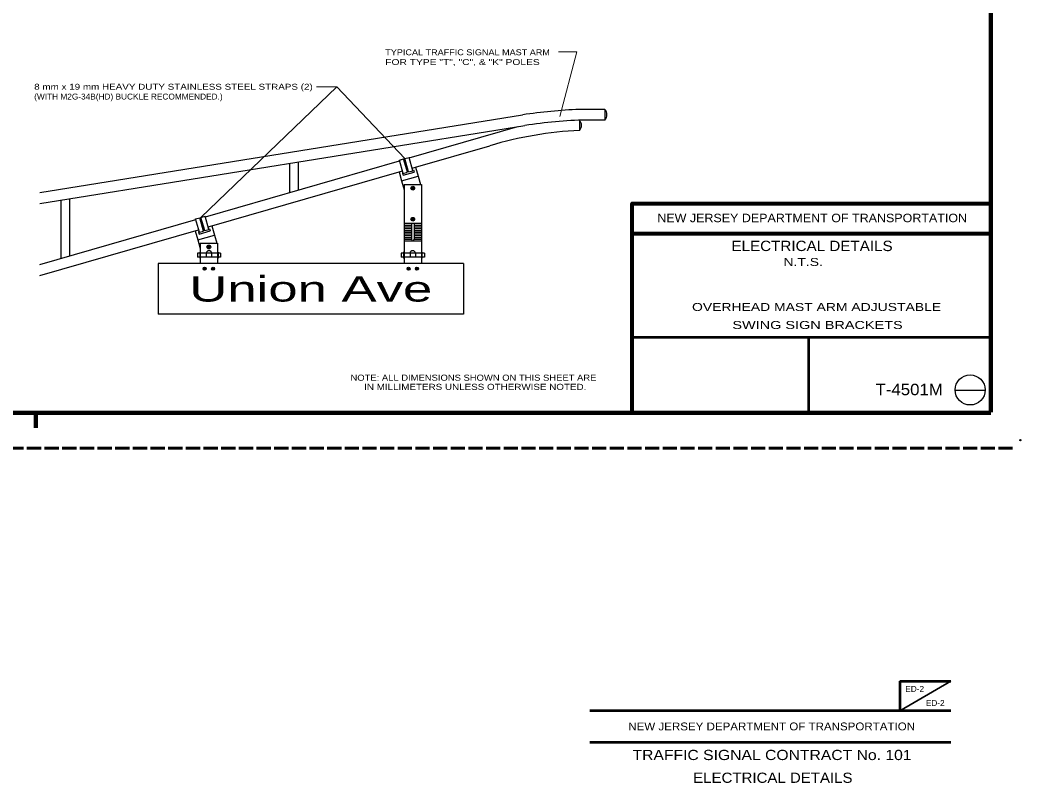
# Model space of a CAD drawing. Extents: x 312583 to 312853, y 144376 to 144586.
# Drawn here: x 312725.3 to 312852.8, y 144375.9 to 144473.1 of the extents above; entities that cross this region are included whole.
import ezdxf
from ezdxf.enums import TextEntityAlignment as Align

# ---------------------------------------------------------------- set-up
doc = ezdxf.new("R2010")
doc.units = 0
doc.header["$LTSCALE"] = 0.3
doc.header["$PDMODE"] = 32
doc.header["$PDSIZE"] = 0.15
doc.linetypes.add('LONG_DASHED', pattern=[7.5, 6, -1.5])
for name, color, linetype, lineweight in [('1', 7, 'Continuous', 25), ('2', 7, 'Continuous', 13), ('25', 7, 'Continuous', 53), ('63', 7, 'LONG_DASHED', 60)]:
    doc.layers.add(name, color=color, linetype=linetype, lineweight=lineweight)

msp = doc.modelspace()

# ---------------------------------------------------------------- hatches: boundary and pattern name
at = {"layer": '1'}
for points in [[(312775.5895, 144451.6938, 1), (312775.1075, 144451.6938, 1)], [(312775.5182, 144451.6938, 1), (312775.1788, 144451.6938, 1)], [(312775.5895, 144447.73, 1), (312775.1075, 144447.73, 1)], [(312775.5182, 144447.73, 1), (312775.1788, 144447.73, 1)], [(312749.6201, 144444.2025, 1), (312749.1381, 144444.2025, 1)], [(312749.5488, 144444.2025, 1), (312749.2094, 144444.2025, 1)], [(312749.0308, 144441.4277, 1), (312748.6485, 144441.4277, 1)], [(312750.1096, 144441.4277, 1), (312749.7273, 144441.4277, 1)], [(312775.0002, 144441.4277, 1), (312774.6179, 144441.4277, 1)], [(312776.079, 144441.4277, 1), (312775.6967, 144441.4277, 1)]]:
    msp.add_hatch(color=256, dxfattribs=at).paths.add_polyline_path(points)

# ---------------------------------------------------------------- linework, layer by layer
at = {"layer": '1', "lineweight": 158}
for p, q in [((312849, 144423.1446), (312849, 144585.0846)), ((312616.5, 144423.0846), (312849, 144423.0846)), ((312727.35, 144421.1646), (312727.35, 144423.0846))]:
    msp.add_line(p, q, dxfattribs=at)
at = {"layer": '1', "lineweight": 13}
for p in [(312748.3619, 144447.9636), (312763.0735, 144464.5977), (312774.337, 144455.4552)]:
    msp.add_line(p, (312765.6556, 144464.5977), dxfattribs=at)
at = {"layer": '1'}
for p, q in [((312799.8122, 144461.7151), (312796.5803, 144461.7151)), ((312799.8122, 144461.7151), (312799.8122, 144460.3724)), ((312727.841, 144451.1213), (312789.348, 144461.0299)), ((312796.5803, 144460.3354), (312796.5803, 144459.0482)), ((312799.8122, 144460.3724), (312797.4323, 144460.3724)), ((312727.841, 144449.7323), (312789.6351, 144459.6779)), ((312774.8927, 144455.5385), (312788.7183, 144459.5297)), ((312775.7168, 144454.3717), (312785.1809, 144457.1035)), ((312748.9267, 144448.0469), (312773.6703, 144455.1866)), ((312773.6518, 144455.2607), (312774.1796, 144455.4089)), ((312774.1333, 144453.5661), (312773.6518, 144455.2607)), ((312774.6797, 144453.7235), (312774.1796, 144455.4089)), ((312774.2074, 144455.344), (312774.3463, 144455.3811)), ((312774.337, 144455.4552), (312774.8741, 144455.6126)), ((312774.8186, 144453.7698), (312774.337, 144455.4552)), ((312775.3557, 144453.9179), (312774.8741, 144455.6126)), ((312759.6317, 144454.8532), (312759.6317, 144451.1306)), ((312760.7614, 144455.0292), (312760.7614, 144451.464)), ((312774.5871, 144454.0476), (312774.726, 144454.0846)), ((312774.8186, 144453.7698), (312775.3557, 144453.9179)), ((312775.2631, 144454.2421), (312775.7168, 144454.3717)), ((312775.3464, 144453.992), (312775.4298, 144454.0198)), ((312775.4298, 144454.0198), (312775.5131, 144453.7327)), ((312775.7168, 144454.3717), (312776.0502, 144453.2142)), ((312749.7509, 144446.8801), (312773.5962, 144453.7605)), ((312773.5962, 144453.7605), (312774.0407, 144453.8809)), ((312773.5962, 144453.7605), (312773.9296, 144452.603)), ((312773.9296, 144452.603), (312776.0502, 144453.2142)), ((312774.0222, 144453.6216), (312774.1055, 144453.6401)), ((312774.0222, 144453.6216), (312774.1055, 144453.3253)), ((312774.1055, 144453.3253), (312775.5131, 144453.7327)), ((312774.1333, 144453.5661), (312774.6797, 144453.7235)), ((312774.6519, 144453.7976), (312774.8001, 144453.8346)), ((312776.0502, 144453.2142), (312776.3465, 144452.177)), ((312773.9296, 144452.603), (312774.2537, 144451.4917)), ((312774.2537, 144452.177), (312774.2537, 144442.0925)), ((312774.2537, 144452.177), (312776.4484, 144452.177)), ((312776.4484, 144452.177), (312776.4484, 144442.0925)), ((312730.508, 144450.1583), (312730.508, 144442.7315)), ((312731.6285, 144450.3435), (312731.6285, 144443.0556)), ((312727.841, 144441.9629), (312747.6951, 144447.695)), ((312747.6766, 144447.7691), (312748.2137, 144447.9173)), ((312748.1674, 144446.0745), (312747.6766, 144447.7691)), ((312748.7045, 144446.2319), (312748.2137, 144447.9173)), ((312748.2415, 144447.8524), (312748.3804, 144447.8895)), ((312748.3619, 144447.9636), (312748.9082, 144448.121)), ((312748.8434, 144446.2782), (312748.3619, 144447.9636)), ((312749.3897, 144446.4356), (312748.9082, 144448.121)), ((312727.841, 144440.5553), (312748.0748, 144446.3893)), ((312747.621, 144446.2689), (312747.9544, 144445.1114)), ((312748.6119, 144446.5467), (312748.76, 144446.593)), ((312748.6767, 144446.306), (312748.8341, 144446.3523)), ((312748.8434, 144446.2782), (312749.3897, 144446.4356)), ((312749.2971, 144446.7505), (312749.7509, 144446.8801)), ((312749.3712, 144446.5004), (312749.4546, 144446.5282)), ((312749.4546, 144446.5282), (312749.5379, 144446.2411)), ((312749.7509, 144446.8801), (312750.0843, 144445.7133)), ((312774.2537, 144447.2505), (312776.4484, 144447.2505)), ((312774.2537, 144446.9912), (312775.1797, 144446.9912)), ((312774.2537, 144446.769), (312775.1797, 144446.769)), ((312774.2537, 144446.5467), (312775.1797, 144446.5467)), ((312774.2537, 144446.3152), (312775.1797, 144446.3152)), ((312775.1797, 144447.2505), (312775.1797, 144445.1947)), ((312775.5131, 144447.2505), (312775.5131, 144445.1947)), ((312775.5131, 144446.9912), (312776.4484, 144446.9912)), ((312775.5131, 144446.769), (312776.4484, 144446.769)), ((312775.5131, 144446.5467), (312776.4484, 144446.5467)), ((312775.5131, 144446.3152), (312776.4484, 144446.3152)), ((312747.9544, 144445.1114), (312750.0843, 144445.7133)), ((312747.9544, 144445.1114), (312748.2785, 144444.0094)), ((312748.0563, 144446.13), (312748.1396, 144446.1485)), ((312748.0563, 144446.13), (312748.1396, 144445.8337)), ((312748.1396, 144445.8337), (312749.5379, 144446.2411)), ((312748.1674, 144446.0745), (312748.7045, 144446.2319)), ((312750.0843, 144445.7133), (312750.3806, 144444.6854)), ((312774.2537, 144446.093), (312775.1797, 144446.093)), ((312774.2537, 144445.8707), (312775.1797, 144445.8707)), ((312774.2537, 144445.6392), (312775.1797, 144445.6392)), ((312774.2537, 144445.417), (312775.1797, 144445.417)), ((312774.2537, 144445.1947), (312775.1797, 144445.1947)), ((312775.5131, 144446.093), (312776.4484, 144446.093)), ((312775.5131, 144445.8707), (312776.4484, 144445.8707)), ((312775.5131, 144445.6392), (312776.4484, 144445.6392)), ((312775.5131, 144445.417), (312776.4484, 144445.417)), ((312775.5131, 144445.1947), (312776.4484, 144445.1947)), ((312748.2785, 144444.6854), (312748.2785, 144442.0925)), ((312748.2785, 144444.6854), (312750.4825, 144444.6854)), ((312750.4825, 144444.6854), (312750.4825, 144442.0925)), ((312774.2537, 144444.9632), (312776.4484, 144444.9632)), ((312747.9081, 144443.389), (312747.9081, 144442.8982)), ((312748.2044, 144443.389), (312747.9081, 144443.389)), ((312748.2044, 144442.8982), (312747.9081, 144442.8982)), ((312748.2044, 144443.5464), (312748.2044, 144442.75)), ((312748.2785, 144443.5464), (312748.2044, 144443.5464)), ((312748.2785, 144442.75), (312748.2044, 144442.75)), ((312750.4825, 144443.389), (312748.2785, 144443.389)), ((312750.4825, 144442.8982), (312748.2785, 144442.8982)), ((312749.0286, 144443.389), (312749.0286, 144442.8982)), ((312749.7324, 144443.389), (312749.7324, 144442.8982)), ((312750.5565, 144443.5464), (312750.4825, 144443.5464)), ((312750.5565, 144442.75), (312750.4825, 144442.75)), ((312750.5565, 144443.5464), (312750.5565, 144442.75)), ((312750.8529, 144443.389), (312750.5565, 144443.389)), ((312750.8529, 144442.8982), (312750.5565, 144442.8982)), ((312750.8529, 144443.389), (312750.8529, 144442.8982)), ((312773.874, 144443.389), (312773.874, 144442.8982)), ((312774.1796, 144443.389), (312773.874, 144443.389)), ((312774.1796, 144442.8982), (312773.874, 144442.8982)), ((312774.1796, 144443.5464), (312774.1796, 144442.75)), ((312774.2537, 144443.5464), (312774.1796, 144443.5464)), ((312774.2537, 144442.75), (312774.1796, 144442.75)), ((312776.4484, 144443.389), (312774.2537, 144443.389)), ((312776.4484, 144442.8982), (312774.2537, 144442.8982)), ((312775.0038, 144443.389), (312775.0038, 144442.8982)), ((312775.6983, 144443.389), (312775.6983, 144442.8982)), ((312776.5225, 144443.5464), (312776.4484, 144443.5464)), ((312776.5225, 144442.75), (312776.4484, 144442.75)), ((312776.5225, 144443.5464), (312776.5225, 144442.75)), ((312776.8281, 144443.389), (312776.5225, 144443.389)), ((312776.8281, 144442.8982), (312776.5225, 144442.8982)), ((312776.8281, 144443.389), (312776.8281, 144442.8982)), ((312781.8194, 144442.0925), (312742.9075, 144442.0925)), ((312742.9075, 144442.0925), (312742.9075, 144435.6196)), ((312781.8194, 144442.0925), (312781.8194, 144435.6196)), ((312781.8194, 144435.6196), (312742.9075, 144435.6196)), ((312844.4384, 144425.966), (312848.2794, 144425.966))]:
    msp.add_line(p, q, dxfattribs=at)
at = {"layer": '1', "lineweight": 80}
msp.add_line((312803.31, 144445.9146), (312849, 144445.9146), dxfattribs=at)
at = {"layer": '1', "lineweight": 53}
for p, q in [((312849, 144432.6666), (312803.31, 144432.6666)), ((312825.7546, 144432.6666), (312825.7546, 144423.1446))]:
    msp.add_line(p, q, dxfattribs=at)
at = {"layer": '1', "lineweight": 80}
msp.add_lwpolyline([(312803.31, 144423.1446), (312803.31, 144449.7246), (312849, 144449.7246)], dxfattribs=at)
at = {"layer": '1'}
for centre, radius in [((312775.3485, 144451.6938), 0.241), ((312775.3485, 144451.6938), 0.1697), ((312775.3485, 144447.73), 0.241), ((312775.3485, 144447.73), 0.1697), ((312749.3791, 144444.2025), 0.241), ((312749.3791, 144444.2025), 0.1697), ((312748.8396, 144441.4277), 0.1911), ((312749.9184, 144441.4277), 0.1911), ((312774.8091, 144441.4277), 0.1911), ((312775.8879, 144441.4277), 0.1911), ((312846.3494, 144425.9805), 1.9159)]:
    msp.add_circle(centre, radius, dxfattribs=at)
for centre, radius, start, end in [((312799.1339, 144397.044), 64.7294, 92.26498, 98.69127), ((312799.1031, 144461.0479), 0.979, 316.42875, 43.57125), ((312799.1361, 144397.5549), 62.8415, 91.54908, 98.69123), ((312795.9388, 144459.6921), 0.9073, 314.6086, 45.3914), ((312799.0242, 144410.3256), 48.782, 92.87671, 106.4991), ((312775.3875, 144445.1763), 0.2096, 174.74074, 259.26749), ((312775.3095, 144445.1763), 0.2096, 280.73251, 5.25926), ((312749.379, 144443.3643), 0.3533, 5.25702, 174.74298), ((312775.3485, 144443.3643), 0.3533, 5.25702, 174.74298)]:
    msp.add_arc(centre, radius, start, end, dxfattribs=at)
msp.add_point((312852.75, 144419.5846), dxfattribs=at)
at = {"layer": '2'}
for p in [(312793.9154, 144469.0709), (312794.0708, 144460.8261)]:
    msp.add_line(p, (312796.2675, 144469.0709), dxfattribs=at)
at = {"layer": '25', "lineweight": 35}
msp.add_line((312837.4089, 144385.1094), (312843.9089, 144388.8594), dxfattribs=at)
at = {"layer": '25'}
for p, q in [((312837.4089, 144388.8594), (312843.9089, 144388.8594)), ((312837.4089, 144388.8594), (312837.4089, 144385.1094)), ((312843.9089, 144385.1094), (312797.9089, 144385.1094)), ((312797.9089, 144381.1094), (312843.9089, 144381.1094))]:
    msp.add_line(p, q, dxfattribs=at)
at = {"layer": '63'}
msp.add_line((312851.75, 144418.5846), (312583.526, 144418.5846), dxfattribs=at)

# ---------------------------------------------------------------- texts
at = {"layer": '1'}
for s, height, width, p in [('NEW JERSEY DEPARTMENT OF TRANSPORTATION', 1.08, 1.1, (312826.2285, 144447.3546)), ('ELECTRICAL DETAILS', 1.315, 1.1, (312826.2107, 144443.6759)), ('Union Ave', 3.236, 1.55, (312762.3588, 144437.2401))]:
    msp.add_text(s, height=height, dxfattribs=dict(at, width=width)).set_placement(p, align=Align.CENTER)
for s, width, p in [('NOTE: ALL DIMENSIONS SHOWN ON THIS SHEET ARE', 1.15, (312767.4173, 144427.151)), ('     IN MILLIMETERS UNLESS OTHERWISE NOTED.', 1.2, (312767.4172, 144425.981))]:
    msp.add_text(s, height=0.78, dxfattribs=dict(at, width=width)).set_placement(p)
at = {"layer": '2'}
for s, width, p in [('TYPICAL TRAFFIC SIGNAL MAST ARM', 1.15, (312771.8479, 144468.6277)), ('FOR TYPE "T", "C", & "K" POLES', 1.3, (312771.8479, 144467.3776)), ('8 mm x 19 mm HEAVY DUTY STAINLESS STEEL STRAPS (2)', 1.25, (312727.1259, 144464.2358)), ('(WITH M2G-34B(HD) BUCKLE RECOMMENDED.)', 1.05, (312727.1259, 144462.9853))]:
    msp.add_text(s, height=0.7505, dxfattribs=dict(at, width=width)).set_placement(p)
for s, height, width, p in [('    N.T.S.  ', 1.02, 1.3, (312824.588, 144441.778)), ('     OVERHEAD MAST ARM ADJUSTABLE    ', 1.02, 1.3, (312826.5399, 144436.0399)), ('      SWING SIGN BRACKETS   ', 1.02, 1.35, (312826.1439, 144433.7476)), ('T-4501M', 1.457, 1.1, (312838.5857, 144425.3122))]:
    msp.add_text(s, height=height, dxfattribs=dict(at, width=width)).set_placement(p, align=Align.CENTER)
at = {"layer": '25'}
for s, height, width, p in [('ED-2', 0.75, 1.05, (312839.2861, 144387.5134)), ('ED-2', 0.75, 1.05, (312841.9054, 144385.724)), ('NEW JERSEY DEPARTMENT OF TRANSPORTATION', 1, 1.1, (312821.0664, 144382.6094)), ('TRAFFIC SIGNAL CONTRACT No. 101', 1.3, 1.15, (312821.1136, 144378.826)), ('ELECTRICAL DETAILS', 1.3, 1.1, (312821.2172, 144375.9236))]:
    msp.add_text(s, height=height, dxfattribs=dict(at, width=width)).set_placement(p, align=Align.CENTER)

doc.saveas('drawing.dxf')
